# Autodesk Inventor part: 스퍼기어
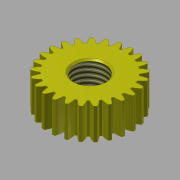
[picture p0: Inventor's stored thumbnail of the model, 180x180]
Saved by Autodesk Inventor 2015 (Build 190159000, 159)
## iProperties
Created: 2017-04
Part Number: 스퍼기어
Material: 강철
Document SubType Name: Modeling
Designer: mduedu
Categories: <?xml version="1.0" encoding="UTF-16"?> <MemberInstance><Categories><FamilyTemplate><FamilyTemplateParameter ValueType="xs:double" Id="1" ObjectReferenceKey="da
Density: 7.85 g/cm^3
Mass: 32.0047 g
Surface Area: 26.9526 cm^2
Volume: 4.07703 cm^3
Appearance: 노란색
CustomPartVersion: 1
Author: mduedu
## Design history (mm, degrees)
sketch "Sketch1"
  geometry: C1 r 13.5 at (0, 0)
  constraints: 1 centre point
  dimensions: "d0" = 27 diameter of C1 (= da_da)
extrude "Extrusion1" new body sketch "Sketch1" distance "d1" = 10 (= da_b); taper "d2" = 0 deg
workplane "Work Plane2"
sketch "Sketch2"
  geometry: C1 r 13.5 at (0, 0) reference; C2 r 12.5 at (0, 0)
  constraints: 1 centre point, 1 coincident
  dimensions: "d3" = 25 diameter of C2 (= da_dw)
feature "피치 지름" sketch "Sketch2" dims "d4" = 10, "d5" = 0
workplane "Work Plane8"
workplane "Work Plane9"
feature "스퍼 기어" dims "da_b" = 10, "da_d" = 25, "da_aw" = 25, "da_da" = 27, "da_df" = 22.5, "da_dw" = 25, angle "da_beta" = 0 deg, "da_lefttooth" = 0, "da_righttooth" = 0
sketch "스케치3"
  geometry: C1 r 5 at (0, 0); 1 further point
  constraints: 1 centre point, 1 coincident
  dimensions: "d49" = 10 diameter of C1
extrude "돌출2" cut sketch "스케치3" stored distance "d50" = 10; taper "d51" = 0 deg
feature "스레드1" dims "d52" = 10, "d53" = 0
chamfer "모따기1" distance "d54" = 0.5; stored, may be unused: second distance "d55" = 2, angle "d56" = 45 deg
body "Solid1"
body "Srf1"
other parameters: "d16" = 25 (= da_aw), "d17" = 0, "d34" = 1.25664 (computed from da_z), "d39" = 0, "d41" = 0, "d43" = 25 (= da_aw), "d46" = 25 (= da_aw), "d47" = 0, "d48" = 0
